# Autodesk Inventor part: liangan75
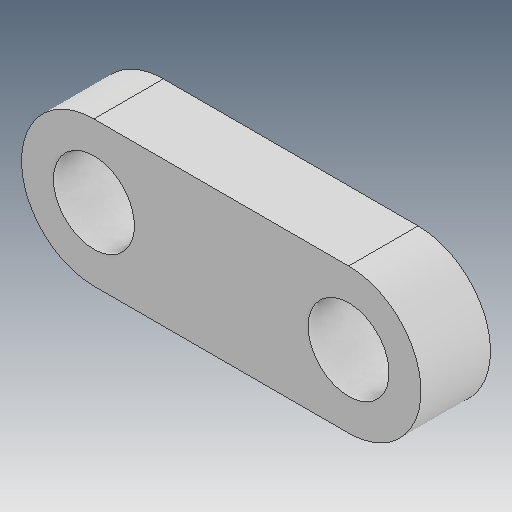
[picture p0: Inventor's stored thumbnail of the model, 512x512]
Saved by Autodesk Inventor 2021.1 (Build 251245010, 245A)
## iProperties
Created: 2018-07
Part Number: liangan75
Material: Ogólny
Document SubType Name: Modeling
Designer: user
Density: 1 g/cm^3
Appearance: Domyślna
Author: user
Revision Number: ÈÎºÎ
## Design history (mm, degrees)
feature "Í¹Ì¨-À­Éì1"
node "Bryła1"
